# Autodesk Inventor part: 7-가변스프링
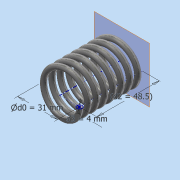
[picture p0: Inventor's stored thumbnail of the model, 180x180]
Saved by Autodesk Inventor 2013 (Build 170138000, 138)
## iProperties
Created: 2014-12
Part Number: 7-가변스프링
Material: 강철, 탄소
Document SubType Name: Modeling
Designer: WINDOWS7
Density: 7.87 g/cm^3
Mass: 70.9949 g
Surface Area: 91.4424 cm^2
Volume: 9.02095 cm^3
Author: WINDOWS7
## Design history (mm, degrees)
sketch "스케치1"
  geometry: L1 (0, 0)-(15.5, 0); L2 (15.5, 0)-(15.5, 48.5); L3 (15.5, 48.5)-(0, 48.5); L4 (0, 48.5)-(0, 0); C1 r 2 at (15.5, 0)
  constraints: 8 end point, 2 parallel, 1 centre point, 1 coincident, 1 horizontal, 1 perpendicular
  dimensions: "d0" = 31 diameter of L2 L4; "d2" = 48.5 distance between parallel lines of L3 L1 (derived); "d3" = 4 diameter of C1
feature "코일1" pitch "d4" = 10; turns "d6" = 7.5; dims "d5" = 48.5 (= d2), "d7" = 0, angle "d8" = 90 deg, angle "d9" = 90 deg, "d10" = 0, "d11" = 0
node "작업 평면1"
sketch "스케치2"
  geometry: L1 (-17.5, 0)-(-13.5, 0) reference; 1 further point
  constraints: 1 horizontal alignment
extrude "돌출1" cut sketch "스케치2" distance "d13" = 10; taper "d14" = 0 deg
node "작업 평면2"
sketch "스케치3"
  geometry: L1 (13.5, 0)-(17.5, 0) reference; 1 further point
  constraints: 1 horizontal alignment
extrude "돌출2" cut sketch "스케치3" distance "d16" = 10; taper "d17" = 0 deg
node "솔리드1"
node "절단 모서리 투영1"
node "절단 모서리 투영2"
other parameters: "d12" = 0, "d15" = 48.5 (= d2)
